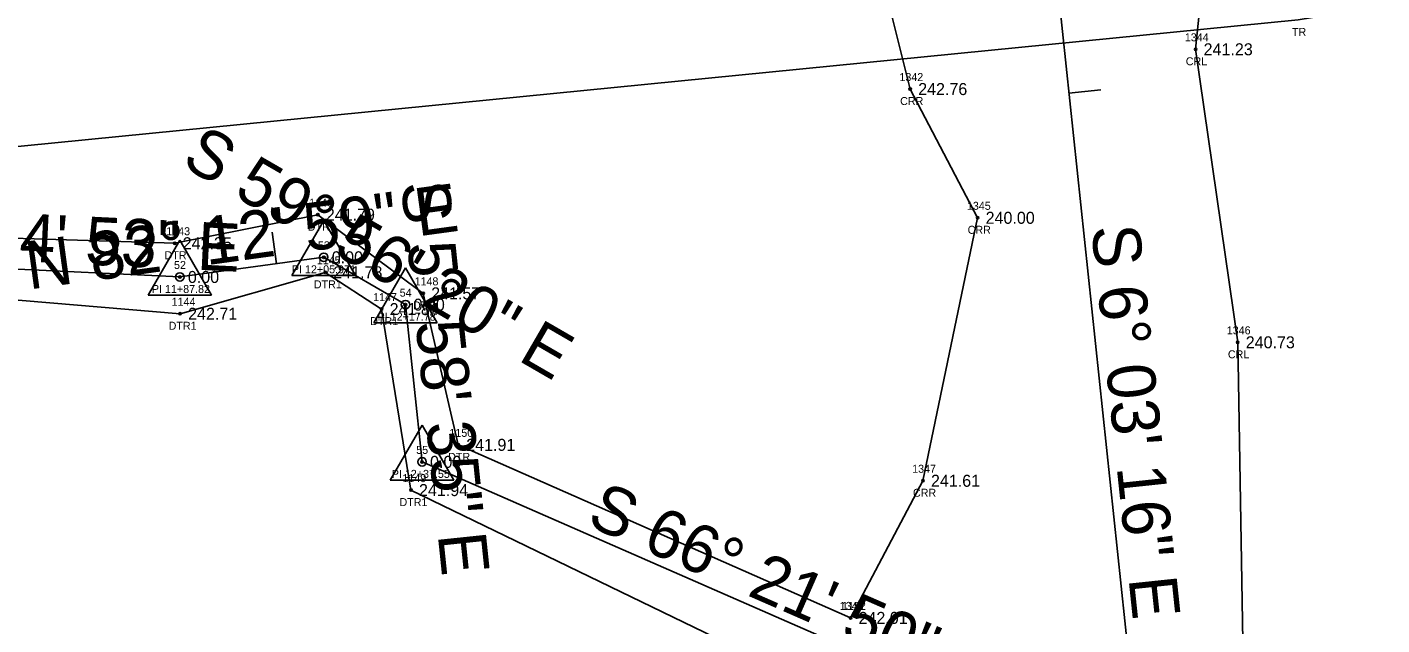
# Model space of a CAD drawing. Extents: x 2274993 to 2278766, y 1075634 to 1076749.
# Drawn here: x 2276227.1 to 2276396.4, y 1075966.5 to 1076041.3 of the extents above; entities that cross this region are included whole.
import ezdxf

# ---------------------------------------------------------------- set-up
doc = ezdxf.new("R2010")
doc.units = 0
for name, color, linetype in [('RD_EX_H2O', 7, 'Continuous'), ('RD_EX_H2O_txCode', 7, 'Continuous'), ('RD_EX_TX_H2O_ELEV', 7, 'Continuous'), ('RD_EX_VEG', 7, 'Continuous'), ('RD_EX_VEG_txCode', 7, 'Continuous'), ('RD_HC_Cl', 7, 'Continuous'), ('RD_HC_Data', 7, 'Continuous'), ('RD_HC_Data_Tic', 7, 'Continuous'), ('RD_HC_Survey_ELEV', 7, 'Continuous'), ('RD_HC_txCode', 7, 'Continuous'), ('RD_SMD_Locator', 7, 'Continuous')]:
    doc.layers.add(name, color=color, linetype=linetype)

msp = doc.modelspace()

# ---------------------------------------------------------------- linework, layer by layer
at = {"layer": 'RD_EX_H2O'}
for points in [[(2276374.66, 1076053.77), (2276373.09, 1076038.49), (2276378.35, 1076001.85), (2276379.41, 1075939.56), (2276393.18, 1075928.69), (2276410.52, 1075916.05), (2276439.66, 1075905.97), (2276458.4, 1075912.38), (2276470.74, 1075911.86), (2276484.27, 1075900.43), (2276472.97, 1075846.67), (2276473.8, 1075804.25), (2276499.15, 1075757.95), (2276529.69, 1075749.92)], [(2276334.2, 1076046.4), (2276337.42, 1076033.52), (2276345.85, 1076017.42), (2276339.02, 1075984.54), (2276329.97, 1075967.39)], [(2275584.42, 1075945.55), (2275630.75, 1075959.99), (2275679.72, 1075972.8), (2275727.1, 1075983.01), (2275776.52, 1075992.46), (2275822.09, 1075998.61), (2275868.31, 1076005.5), (2275971.07, 1076013.85), (2276058.03, 1076018.84), (2276110, 1076025.4), (2276114.25, 1076022.31), (2276152.59, 1076021.64), (2276188.46, 1076022.22), (2276200.36, 1076021.35), (2276207.63, 1076015.4), (2276245.53, 1076014.24), (2276263.41, 1076017.81), (2276276.57, 1076007.97), (2276280.95, 1075989.03), (2276329.97, 1075967.39)], [(2275587.87, 1075932.23), (2275632.3, 1075945.74), (2275680.34, 1075962.3), (2275730.43, 1075971.98), (2275777.84, 1075981.49), (2275823.91, 1075987.34), (2275869.26, 1075992.75), (2275941.88, 1076000), (2275968.29, 1076005.71), (2275973.41, 1076009.09), (2276058.49, 1076013.63), (2276114.54, 1076018.47), (2276125.61, 1076012.99), (2276153.29, 1076014.06), (2276186.69, 1076017.67), (2276196.76, 1076016.05), (2276210.13, 1076008.45), (2276246.2, 1076005.42), (2276264.34, 1076010.6), (2276271.38, 1076006), (2276275.05, 1075983.37), (2276331.39, 1075956.06)]]:
    msp.add_lwpolyline(points, dxfattribs=at)
at = {"layer": 'RD_EX_VEG'}
msp.add_lwpolyline([(2275588.01, 1075931.75), (2275680.64, 1075961.35), (2275730.55, 1075971.06), (2275824.32, 1075986.29), (2275869.68, 1075991.08), (2276385.92, 1076042.16), (2276665.98, 1076087.69), (2276721.29, 1076100.17), (2276841.99, 1076132.87), (2276855.5, 1076106.15)], dxfattribs=at)
at = {"layer": 'RD_HC_Cl'}
for p, q in [((2276355.37, 1076050.89), (2276368.02, 1075931.61)), ((2276355.37, 1076050.89), (2276368.02, 1075931.61)), ((2276207.46, 1076011.88), (2276246.17, 1076010.02)), ((2276246.17, 1076010.02), (2276264.15, 1076012.48)), ((2276264.15, 1076012.48), (2276274.37, 1076006.56)), ((2276274.37, 1076006.56), (2276276.43, 1075986.9)), ((2276276.43, 1075986.9), (2276366.32, 1075947.56))]:
    msp.add_line(p, q, dxfattribs=at)
at = {"layer": 'RD_HC_Data'}
for p, q in [((2276260.18, 1076010.19), (2276264.16, 1076017.07)), ((2276264.16, 1076017.07), (2276268.12, 1076010.19)), ((2276242.2, 1076007.73), (2276246.18, 1076014.61)), ((2276246.18, 1076014.61), (2276250.14, 1076007.73)), ((2276270.4, 1076004.27), (2276274.38, 1076011.15)), ((2276274.38, 1076011.15), (2276278.34, 1076004.27)), ((2276260.18, 1076010.19), (2276268.12, 1076010.19)), ((2276242.2, 1076007.73), (2276250.14, 1076007.73)), ((2276270.4, 1076004.27), (2276278.34, 1076004.27)), ((2276272.46, 1075984.6), (2276276.43, 1075991.48)), ((2276276.43, 1075991.48), (2276280.4, 1075984.6)), ((2276272.46, 1075984.6), (2276280.4, 1075984.6))]:
    msp.add_line(p, q, dxfattribs=at)
for centre in [(2276264.15, 1076012.48), (2276246.17, 1076010.02), (2276274.37, 1076006.56), (2276276.43, 1075986.9)]:
    msp.add_circle(centre, 0.529, dxfattribs=at)
at = {"layer": 'RD_HC_Data_Tic'}
for p, q in [((2276357.26, 1076032.99), (2276361.24, 1076033.41)), ((2276258.24, 1076011.67), (2276257.7, 1076015.63))]:
    msp.add_line(p, q, dxfattribs=at)
at = {"layer": 'RD_SMD_Locator'}
for centre in [(2276373.09, 1076038.49), (2276337.42, 1076033.52), (2276263.41, 1076017.81), (2276345.85, 1076017.42), (2276245.53, 1076014.24), (2276264.15, 1076012.48), (2276246.17, 1076010.02), (2276264.34, 1076010.6), (2276276.57, 1076007.97), (2276271.38, 1076006), (2276274.37, 1076006.56), (2276246.2, 1076005.42), (2276378.35, 1076001.85), (2276280.95, 1075989.03), (2276276.43, 1075986.9), (2276339.02, 1075984.54), (2276275.05, 1075983.37), (2276329.97, 1075967.39), (2276329.97, 1075967.39)]:
    msp.add_circle(centre, 0.15, dxfattribs=at)

# ---------------------------------------------------------------- texts
at = {"layer": 'RD_EX_H2O_txCode'}
for s, p in [('1344', (2276371.74, 1076039.49)), ('CRL', (2276371.86, 1076036.49)), ('1342', (2276336.08, 1076034.52)), ('CRR', (2276336.17, 1076031.52)), ('1146', (2276262.33, 1076018.81)), ('1345', (2276344.51, 1076018.42)), ('1143', (2276244.47, 1076015.24)), ('DTR', (2276262.15, 1076015.81)), ('CRR', (2276344.6, 1076015.42)), ('DTR', (2276244.26, 1076012.24)), ('1145', (2276263.28, 1076011.6)), ('DTR1', (2276262.91, 1076008.6)), ('1148', (2276275.5, 1076008.97)), ('1144', (2276245.14, 1076006.42)), ('1147', (2276270.32, 1076007)), ('DTR', (2276275.3, 1076005.97)), ('DTR1', (2276244.77, 1076003.42)), ('DTR1', (2276269.95, 1076004)), ('1346', (2276376.98, 1076002.85)), ('CRL', (2276377.12, 1075999.85)), ('1150', (2276279.85, 1075990.03)), ('DTR', (2276279.69, 1075987.03)), ('1347', (2276337.67, 1075985.54)), ('1149', (2276273.98, 1075984.37)), ('DTR1', (2276273.61, 1075981.37)), ('CRR', (2276337.77, 1075982.54)), ('1348', (2276328.62, 1075968.39)), ('1152', (2276328.91, 1075968.39))]:
    msp.add_text(s, height=1, dxfattribs=at).set_placement(p)
at = {"layer": 'RD_EX_TX_H2O_ELEV'}
for s, p in [('241.23', (2276374.09, 1076037.74)), ('242.76', (2276338.42, 1076032.77)), ('241.79', (2276264.41, 1076017.06)), ('240.00', (2276346.85, 1076016.67)), ('242.35', (2276246.53, 1076013.49)), ('241.78', (2276265.34, 1076009.85)), ('241.57', (2276277.57, 1076007.22)), ('242.71', (2276247.2, 1076004.67)), ('241.84', (2276272.38, 1076005.25)), ('240.73', (2276379.35, 1076001.1)), ('241.91', (2276281.95, 1075988.28)), ('241.94', (2276276.05, 1075982.62)), ('241.61', (2276340.02, 1075983.79)), ('242.01', (2276330.97, 1075966.64)), ('242.01', (2276330.97, 1075966.64))]:
    msp.add_text(s, height=1.5, dxfattribs=at).set_placement(p)
at = {"layer": 'RD_EX_VEG_txCode'}
msp.add_text('TR', height=1, dxfattribs=at).set_placement((2276385.13, 1076040.16))
at = {"layer": 'RD_HC_Data'}
for s, rotation, p in [('S 59%%d 56\' 20" E', 329.9389, (2276246.19, 1076024.03)), ('N 82%%d 12\' 59" E', 7.7836, (2276227.31, 1076008.45)), ('S 5%%d 58\' 35" E', 275.9763, (2276273.79, 1076021.74)), ('S 87%%d 14\' 53" E', 357.2479, (2276199.66, 1076013.26)), ('S 6%%d 03\' 16" E', 276.0543, (2276360.04, 1076016.26)), ('S 6%%d 03\' 16" E', 276.0543, (2276360.04, 1076016.26)), ('S 66%%d 21\' 50" E', 336.364, (2276296.82, 1075979.06))]:
    msp.add_text(s, height=6, rotation=rotation, dxfattribs=at).set_placement(p)
at = {"layer": 'RD_HC_Survey_ELEV'}
for p in [(2276265.15, 1076011.73), (2276247.17, 1076009.27), (2276275.37, 1076005.81), (2276277.43, 1075986.15)]:
    msp.add_text('0.00', height=1.5, dxfattribs=at).set_placement(p)
at = {"layer": 'RD_HC_txCode'}
for s, p in [('53', (2276263.42, 1076013.48)), ('52', (2276245.44, 1076011.02)), ('PI 12+05.971', (2276260.17, 1076010.48)), ('PI 11+87.82', (2276242.68, 1076008.02)), ('54', (2276273.64, 1076007.56)), ('PI 12+17.78', (2276270.88, 1076004.56)), ('55', (2276275.7, 1075987.9)), ('PI 12+37.55', (2276272.65, 1075984.9))]:
    msp.add_text(s, height=1, dxfattribs=at).set_placement(p)

doc.saveas('drawing.dxf')
